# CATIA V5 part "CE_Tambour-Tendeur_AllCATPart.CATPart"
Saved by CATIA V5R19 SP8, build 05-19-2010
Part number: CE17_Tambour-Tendeur_AllCATPart
Bounding box of the stored display mesh (mm): x -235 to 235, y 1496.646 to 1538.605, z 98.521 to 140.479
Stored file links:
  D:\Documents\1_Travail\1 - ac-limoges.fr\ac-limoges.fr\Emmanuel Maynard - STI2D_Turgot\2 -2I2D\1_SEQUENCE_ Tapis_de_course\3- Spécificités\Spé_ITEC\3-Pente\Tapis_TC520B_Pente\CE_Tambour-Tendeur_AllCATPart.CATPart
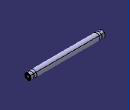
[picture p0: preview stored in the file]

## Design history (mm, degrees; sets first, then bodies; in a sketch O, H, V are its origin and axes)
AxisSystem1: origin (0, 0, 0), X (1, 0, 0), Y (0, 1, 0), Z (0, 0, 1)
Body1 (main body)
Body2 "snr_62202ee_1_1.1"
  Solid1: solid without history
  Body3 "snr_62202ee_1_1.1\\snr_62202ee_1_2"
    Solid2 "Solide.1": solid without history
  Add1 "snr_62202ee_1_1.1\\snr_62202ee_1_2": tool Body3
  Body4 "snr_62202ee_1_1.1\\snr_62202ee_1_3"
    Solid3 "Solide.1": solid without history
  Add2 "snr_62202ee_1_1.1\\snr_62202ee_1_3": tool Body4
  Body5 "snr_62202ee_1_1.1\\snr_62202ee_1_4"
    Solid4 "Solide.1": solid without history
  Add3 "snr_62202ee_1_1.1\\snr_62202ee_1_4": tool Body5
  Body6 "snr_62202ee_1_1.1\\snr_62202ee_1_5"
    Solid5 "Solide.1": solid without history
  Add4 "snr_62202ee_1_1.1\\snr_62202ee_1_5": tool Body6
Body7 "snr_62202ee_1_1.2"
  Solid6 "Solide.1": solid without history
  Body8 "snr_62202ee_1_1.2\\snr_62202ee_1_2"
    Solid7 "Solide.1": solid without history
  Add5 "snr_62202ee_1_1.2\\snr_62202ee_1_2": tool Body8
  Body9 "snr_62202ee_1_1.2\\snr_62202ee_1_3"
    Solid8 "Solide.1": solid without history
  Add6 "snr_62202ee_1_1.2\\snr_62202ee_1_3": tool Body9
  Body10 "snr_62202ee_1_1.2\\snr_62202ee_1_4"
    Solid9 "Solide.1": solid without history
  Add7 "snr_62202ee_1_1.2\\snr_62202ee_1_4": tool Body10
  Body11 "snr_62202ee_1_1.2\\snr_62202ee_1_5"
    Solid10 "Solide.1": solid without history
  Add8 "snr_62202ee_1_1.2\\snr_62202ee_1_5": tool Body11
Body12 "Tambour_Tendeur.1\\Corps principal"
  Solid11 "Solide.1": solid without history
